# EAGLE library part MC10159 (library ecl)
Quad 2-input Multiplexer (inverting)
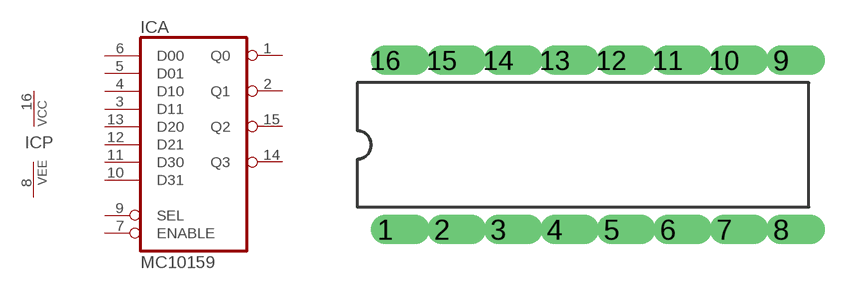
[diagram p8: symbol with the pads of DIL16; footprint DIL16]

Designator prefix IC; gates A=MC10159 P=1VCC1VEE

## MC10159  [DIL16]
1  A:Q0  out
2  A:Q1  out
3  A:D11  in
4  A:D10  in
5  A:D01  in
6  A:D00  in
7  A:ENABLE  in
8  P:VEE  pwr
9  A:SEL  in
10  A:D31  in
11  A:D30  in
12  A:D21  in
13  A:D20  in
14  A:Q3  out
15  A:Q2  out
16  P:VCC  pwr

## Footprint DIL16 (pad centres in mm)
drill 0.813 offset: 1 -8.89,-3.81; 2 -6.35,-3.81; 3 -3.81,-3.81; 4 -1.27,-3.81; 5 1.27,-3.81; 6 3.81,-3.81; 7 6.35,-3.81; 8 8.89,-3.81; 9 8.89,3.81; 10 6.35,3.81; 11 3.81,3.81; 12 1.27,3.81; 13 -1.27,3.81; 14 -3.81,3.81; 15 -6.35,3.81; 16 -8.89,3.81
